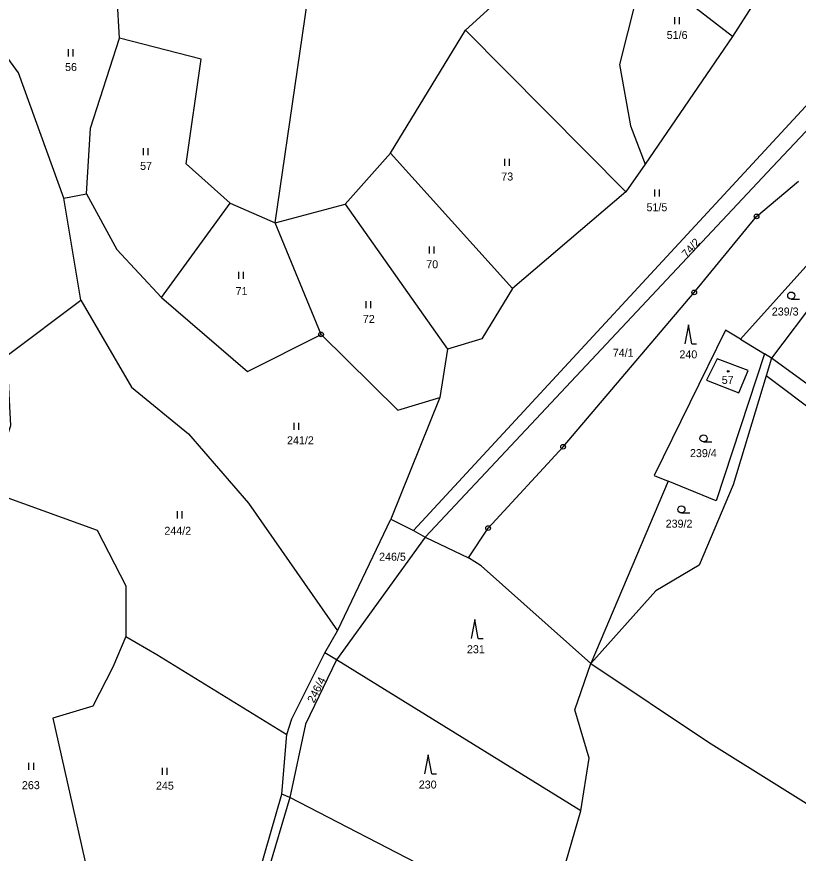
# Model space of a CAD drawing. Extents: x -680203 to -673936, y -1102717 to -1093650.
# Drawn here: x -675221.6 to -675055.6, y -1100217.9 to -1100040.2 of the extents above; entities that cross this region are included whole.
import ezdxf

# ---------------------------------------------------------------- set-up
doc = ezdxf.new("R2010")
doc.units = 0
for name, color, linetype in [('_Ideová část', 7, 'Continuous'), ('SOxx02xx_Koleje_param další_Popis10', 7, 'Continuous'), ('SOxxxxxx_Koleje_hlavní_body_Popis10', 7, 'Continuous'), ('SOxxxxxx_Koleje_param další_Popis10', 7, 'Continuous'), ('SOxxxxxx_Osa_bod_P', 7, 'Continuous'), ('x_prac', 7, 'Continuous')]:
    doc.layers.add(name, color=color, linetype=linetype)

msp = doc.modelspace()

# ---------------------------------------------------------------- linework, layer by layer
at = {"layer": '_Ideová část'}
msp.add_circle((-676417.7, -1099401.52), 1287.12, dxfattribs=at)
at = {"layer": 'SOxx02xx_Koleje_param další_Popis10'}
for centre, radius in [((-675064.46, -1100082.65), 0.5), ((-675064.46, -1100082.65), 0.0303), ((-675077.7, -1100098.81), 0.5), ((-675077.7, -1100098.81), 0.0303), ((-675156.95, -1100107.74), 0.5), ((-675156.95, -1100107.74), 0.0303), ((-675105.54, -1100131.59), 0.5), ((-675105.54, -1100131.59), 0.0303), ((-675121.47, -1100148.87), 0.5), ((-675121.47, -1100148.87), 0.0303)]:
    msp.add_circle(centre, radius, dxfattribs=at)
at = {"layer": 'SOxxxxxx_Koleje_hlavní_body_Popis10'}
for p, q in [((-675081.8, -1100041.83), (-675081.8, -1100040.33)), ((-675080.8, -1100041.83), (-675080.8, -1100040.33)), ((-675210.56, -1100048.65), (-675210.56, -1100047.15)), ((-675209.56, -1100048.65), (-675209.56, -1100047.15)), ((-675194.66, -1100069.64), (-675194.66, -1100068.14)), ((-675193.66, -1100069.64), (-675193.66, -1100068.14)), ((-675117.92, -1100071.91), (-675117.92, -1100070.41)), ((-675116.92, -1100071.91), (-675116.92, -1100070.41)), ((-675086.04, -1100078.44), (-675086.04, -1100076.94)), ((-675085.04, -1100078.44), (-675085.04, -1100076.94)), ((-675133.91, -1100090.54), (-675133.91, -1100089.04)), ((-675132.91, -1100090.54), (-675132.91, -1100089.04)), ((-675174.39, -1100095.91), (-675174.39, -1100094.41)), ((-675173.39, -1100095.91), (-675173.39, -1100094.41)), ((-675147.34, -1100102.17), (-675147.34, -1100100.67)), ((-675146.34, -1100102.17), (-675146.34, -1100100.67)), ((-675057.1, -1100100.22), (-675055.35, -1100100.22)), ((-675078.93, -1100105.69), (-675079.68, -1100109.69)), ((-675078.18, -1100109.69), (-675078.93, -1100105.69)), ((-675078.18, -1100109.69), (-675077.18, -1100109.69)), ((-675162.68, -1100128.02), (-675162.68, -1100126.52)), ((-675161.68, -1100128.02), (-675161.68, -1100126.52)), ((-675075.72, -1100130.56), (-675073.97, -1100130.56)), ((-675187.43, -1100146.8), (-675187.43, -1100145.3)), ((-675186.43, -1100146.8), (-675186.43, -1100145.3)), ((-675080.41, -1100145.66), (-675078.66, -1100145.66)), ((-675124.3, -1100168.32), (-675125.05, -1100172.32)), ((-675123.55, -1100172.32), (-675124.3, -1100168.32)), ((-675123.55, -1100172.32), (-675122.55, -1100172.32)), ((-675134.2, -1100197.07), (-675134.95, -1100201.07)), ((-675133.45, -1100201.07), (-675134.2, -1100197.07)), ((-675218.97, -1100200.24), (-675218.97, -1100198.74)), ((-675217.97, -1100200.24), (-675217.97, -1100198.74)), ((-675190.59, -1100201.3), (-675190.59, -1100199.8)), ((-675189.59, -1100201.3), (-675189.59, -1100199.8)), ((-675133.45, -1100201.07), (-675132.45, -1100201.07))]:
    msp.add_line(p, q, dxfattribs=at)
for centre in [(-675057.1, -1100099.47), (-675075.72, -1100129.81), (-675080.41, -1100144.91)]:
    msp.add_circle(centre, 0.75, dxfattribs=at)
at = {"layer": 'SOxxxxxx_Koleje_param další_Popis10'}
msp.add_circle((-675070.47, -1100115.57), 0.175, dxfattribs=at)
at = {"layer": 'x_prac'}
for p, q in [((-675055.77, -1100022.67), (-675069.57, -1100044.46)), ((-675199.76, -1100044.77), (-675200.72, -1100028.54)), ((-675036.37, -1100040.14), (-675137.31, -1100149.35)), ((-675142.2, -1100069.24), (-675126.26, -1100043.08)), ((-675126.26, -1100043.08), (-675092.23, -1100077.45)), ((-675069.57, -1100044.46), (-675088.08, -1100071.59)), ((-675151.81, -1100080.04), (-675142.2, -1100069.24)), ((-675116.3, -1100097.94), (-675142.2, -1100069.24)), ((-675088.08, -1100071.59), (-675092.23, -1100077.45)), ((-675211.57, -1100078.76), (-675206.76, -1100077.84)), ((-675207.93, -1100100.43), (-675211.57, -1100078.76)), ((-675092.23, -1100077.45), (-675116.3, -1100097.94)), ((-675190.81, -1100099.88), (-675176.24, -1100079.87)), ((-675176.24, -1100079.87), (-675166.72, -1100084.02)), ((-675166.72, -1100084.02), (-675151.81, -1100080.04)), ((-675151.81, -1100080.04), (-675130.08, -1100110.87)), ((-675156.95, -1100107.74), (-675166.72, -1100084.02)), ((-675048.5, -1100087.12), (-675067.89, -1100108.73)), ((-675047.98, -1100095.04), (-675061.25, -1100112.79)), ((-675207.93, -1100100.43), (-675197.2, -1100118.95)), ((-675067.89, -1100108.73), (-675062.75, -1100111.87)), ((-675130.08, -1100110.87), (-675131.7, -1100121.11)), ((-675061.25, -1100112.79), (-675062.75, -1100111.87)), ((-675061.25, -1100112.79), (-675062.39, -1100116.55)), ((-674970.67, -1100178.88), (-675061.25, -1100112.79)), ((-675131.7, -1100121.11), (-675142.16, -1100146.94)), ((-675083.24, -1100138.91), (-675099.65, -1100177.65)), ((-675153.47, -1100170.68), (-675142.16, -1100146.94)), ((-675142.16, -1100146.94), (-675137.31, -1100149.35)), ((-675137.31, -1100149.35), (-675134.81, -1100150.78)), ((-675134.81, -1100150.78), (-675153.64, -1100176.83)), ((-675134.81, -1100150.78), (-675125.65, -1100155.2)), ((-675156.13, -1100175.35), (-675153.47, -1100170.68)), ((-675153.64, -1100176.83), (-675156.13, -1100175.35)), ((-675101.79, -1100208.93), (-675153.64, -1100176.83)), ((-675165.25, -1100205.38), (-675164.21, -1100192.75)), ((-675178.12, -1100249.61), (-675165.25, -1100205.38)), ((-675163.55, -1100206.09), (-675176.83, -1100250.75)), ((-675163.55, -1100206.09), (-675165.25, -1100205.38)), ((-675109.17, -1100234.21), (-675163.55, -1100206.09)), ((-675109.17, -1100234.21), (-675101.79, -1100208.93))]:
    msp.add_line(p, q, dxfattribs=at)
for points in [[(-675166.72, -1100084.02), (-675157.18, -1100018.83), (-675189.64, -1100012.91), (-675190.09, -1100009.88), (-675223.66, -1100004.74)], [(-675126.26, -1100043.08), (-675109.29, -1100027.56), (-675102.55, -1100023.38)], [(-675069.57, -1100044.46), (-675088.41, -1100029.86), (-675093.58, -1100050.4), (-675091.22, -1100063.42), (-675088.08, -1100071.59)], [(-675211.57, -1100078.76), (-675221.23, -1100052.13), (-675229.35, -1100041.03)], [(-675206.76, -1100077.84), (-675205.9, -1100063.93), (-675199.76, -1100044.77)], [(-675176.24, -1100079.87), (-675185.62, -1100071.49), (-675182.37, -1100049.26), (-675199.76, -1100044.77)], [(-675034.16, -1100043.59), (-675061.09, -1100072.11), (-675134.81, -1100150.78)], [(-675125.65, -1100155.2), (-675121.47, -1100148.87), (-675105.54, -1100131.59), (-675077.7, -1100098.81), (-675064.46, -1100082.65), (-675055.57, -1100075.18)], [(-675206.76, -1100077.84), (-675200.34, -1100089.7), (-675190.81, -1100099.88)], [(-675116.3, -1100097.94), (-675122.78, -1100108.64), (-675130.08, -1100110.87)], [(-675190.81, -1100099.88), (-675172.55, -1100115.63), (-675156.95, -1100107.74)], [(-675227.61, -1100140.95), (-675222.85, -1100127.09), (-675223.59, -1100112.18), (-675207.93, -1100100.43)], [(-675067.89, -1100108.73), (-675071.06, -1100106.79), (-675086.21, -1100137.73), (-675083.24, -1100138.91)], [(-675156.95, -1100107.74), (-675140.67, -1100123.82), (-675131.7, -1100121.11)], [(-675062.75, -1100111.87), (-675073.02, -1100143.11), (-675083.24, -1100138.91)], [(-675066.26, -1100115.41), (-675072.79, -1100112.88), (-675075.1, -1100117.41), (-675068.21, -1100120.12), (-675066.26, -1100115.41)], [(-675062.39, -1100116.55), (-675069.4, -1100139.67), (-675076.66, -1100156.77), (-675085.86, -1100162.23), (-675099.65, -1100177.65)], [(-674967.49, -1100185.55), (-675017.09, -1100150.59), (-675062.39, -1100116.55)], [(-675197.2, -1100118.95), (-675185.08, -1100128.82), (-675172.36, -1100143.55), (-675153.47, -1100170.68)], [(-675227.61, -1100140.95), (-675204.48, -1100149.34), (-675198.43, -1100161.15), (-675198.38, -1100171.91)], [(-675099.65, -1100177.65), (-675122.97, -1100156.86), (-675125.65, -1100155.2)], [(-675198.38, -1100171.91), (-675201.13, -1100178.38), (-675205.39, -1100186.69), (-675213.92, -1100189.27), (-675206.51, -1100221.93), (-675201.91, -1100230.01), (-675205.95, -1100240.56)], [(-675198.38, -1100171.91), (-675191.81, -1100175.72), (-675164.21, -1100192.75)], [(-675164.21, -1100192.75), (-675163.15, -1100189.42), (-675156.13, -1100175.35)], [(-675153.64, -1100176.83), (-675160.24, -1100190.49), (-675163.55, -1100206.09)], [(-675101.79, -1100208.93), (-675100.02, -1100197.72), (-675103.02, -1100187.46), (-675099.65, -1100177.65)], [(-675099.65, -1100177.65), (-675074.67, -1100194.35), (-674979.11, -1100254.05), (-674908.72, -1100300.19)]]:
    msp.add_lwpolyline(points, dxfattribs=at)

# ---------------------------------------------------------------- texts
at = {"layer": 'SOxxxxxx_Osa_bod_P'}
for s, p in [('51/6', (-675083.54, -1100044.96)), ('56', (-675211.31, -1100051.77)), ('57', (-675195.37, -1100072.77)), ('73', (-675118.67, -1100075.03)), ('51/5', (-675087.83, -1100081.56)), ('70', (-675134.6, -1100093.67)), ('71', (-675175.1, -1100099.38)), ('239/3', (-675061.22, -1100103.71)), ('72', (-675148.07, -1100105.29)), ('74/1', (-675094.99, -1100112.48)), ('240', (-675080.84, -1100112.81)), ('57', (-675071.85, -1100118.24)), ('241/2', (-675164.17, -1100131.07)), ('239/4', (-675078.6, -1100133.79)), ('239/2', (-675083.76, -1100148.78)), ('244/2', (-675190.22, -1100150.29)), ('246/5', (-675144.62, -1100155.8)), ('231', (-675125.96, -1100175.45)), ('263', (-675220.47, -1100204.33)), ('245', (-675192.01, -1100204.43)), ('230', (-675136.19, -1100204.2))]:
    msp.add_text(s, height=1.7, dxfattribs=at).set_placement(p)
for s, rotation, p in [('74/2', 48, (-675079.26, -1100091.55)), ('246/4', 63, (-675158.45, -1100186.14))]:
    msp.add_text(s, height=1.7, rotation=rotation, dxfattribs=at).set_placement(p)

doc.saveas('drawing.dxf')
